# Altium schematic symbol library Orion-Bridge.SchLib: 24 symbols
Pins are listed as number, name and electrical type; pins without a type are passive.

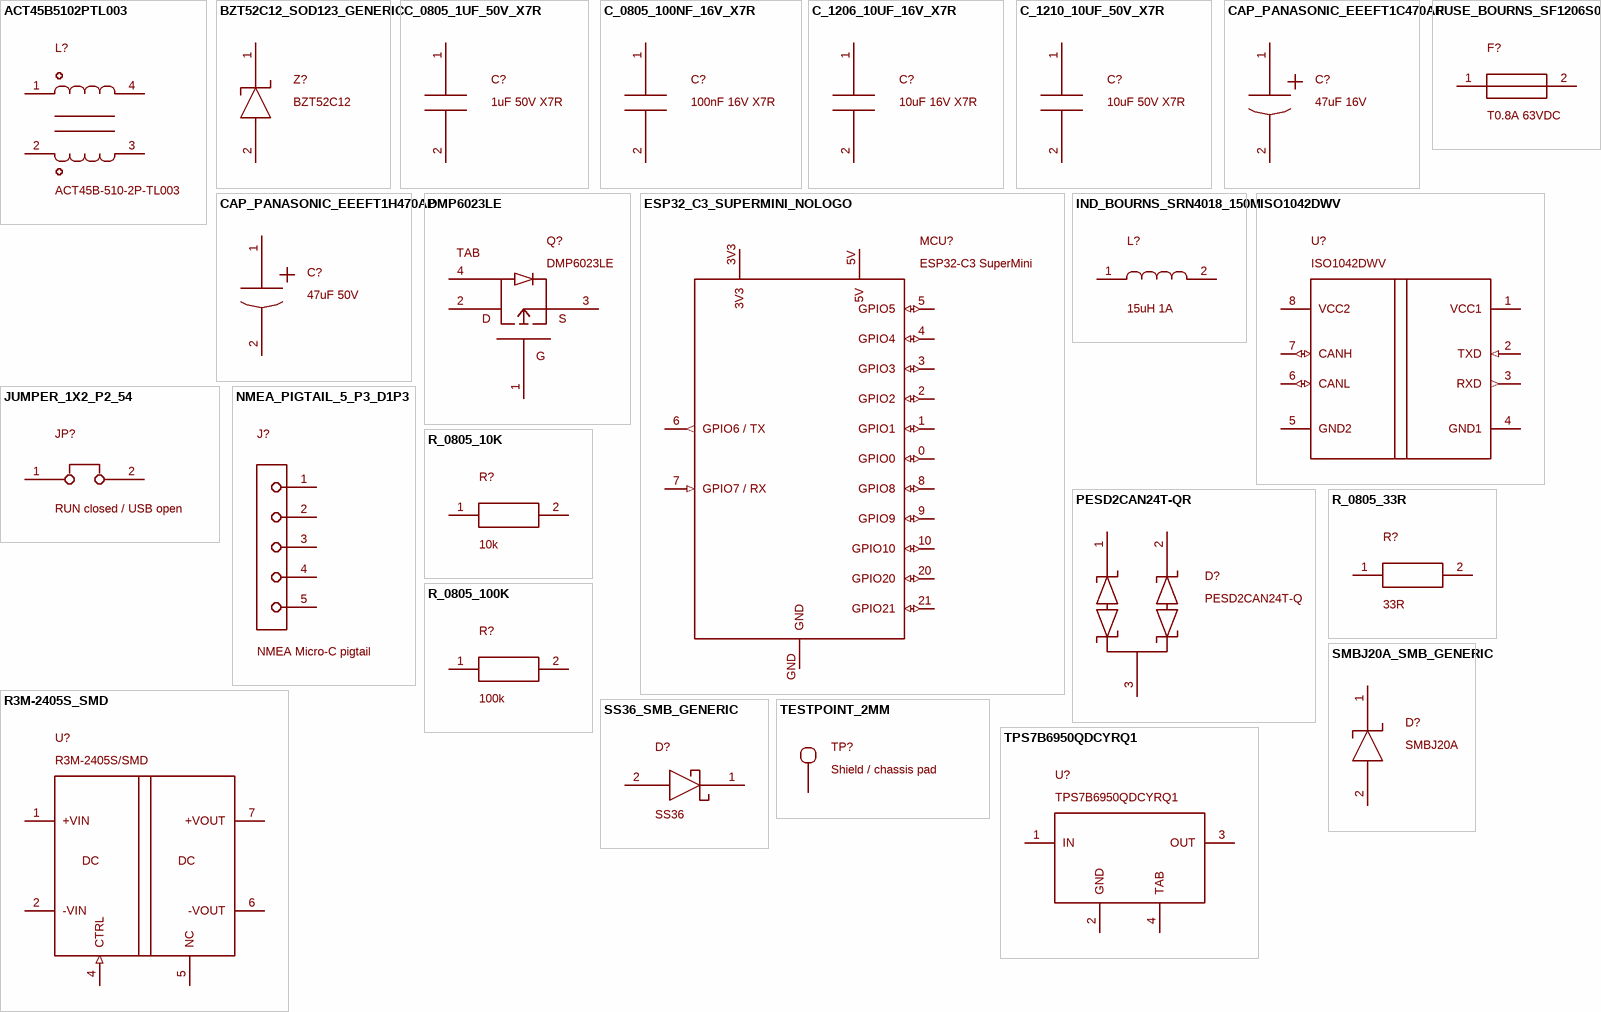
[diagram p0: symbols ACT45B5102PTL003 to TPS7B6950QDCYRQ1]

## ACT45B5102PTL003
designator L?, comment ACT45B-510-2P-TL003
Manufacturer: TDK; MPN: ACT45B5102PTL003
footprint ACT45B
pins: 1 H_EXT, 2 L_EXT, 3 L_IC, 4 H_IC

## BZT52C12_SOD123_GENERIC
designator Z?, comment BZT52C12
BZT52C12 - generic specification; manufacturer/MPN not selected
footprint SOD123
pins: 1 K, 2 A

## C_0805_1UF_50V_X7R
designator C?, comment 1uF 50V X7R
1uF 50V X7R - generic specification; manufacturer/MPN not selected
footprint C0805
pins: 1, 2

## C_0805_100NF_16V_X7R
designator C?, comment 100nF 16V X7R
100nF 16V X7R - generic specification; manufacturer/MPN not selected
footprint C0805
pins: 1, 2

## C_1206_10UF_16V_X7R
designator C?, comment 10uF 16V X7R
10uF 16V X7R - generic specification; manufacturer/MPN not selected
footprint C1206
pins: 1, 2

## C_1210_10UF_50V_X7R
designator C?, comment 10uF 50V X7R
10uF 50V X7R - generic specification; manufacturer/MPN not selected
footprint C1210
pins: 1, 2

## CAP_PANASONIC_EEEFT1C470AR
designator C?, comment 47uF 16V
47 uF 16 V FT-series SMD aluminum electrolytic, size B, standard product; Manufacturer: Panasonic Industry; MPN: EEEFT1C470AR
footprint PANASONIC_FT_D4
pins: 1 +, 2 -

## CAP_PANASONIC_EEEFT1H470AP
designator C?, comment 47uF 50V
47 uF 50 V FT-series SMD aluminum electrolytic, size D, standard product; Manufacturer: Panasonic Industry; MPN: EEEFT1H470AP
footprint PANASONIC_FT_D6P3
pins: 1 +, 2 -

## DMP6023LE
designator Q?
Manufacturer: Diodes Incorporated
footprint SOT223_DIODES_DMP6023LE
pins: 1 G, 2 D, 3 S, 4 TAB=D

## ESP32_C3_SUPERMINI_NOLOGO
designator MCU?, comment ESP32-C3 SuperMini
Nologo ESP32-C3 SuperMini module, two 1x8 carrier headers, GPIO6 TX / GPIO7 RX; Manufacturer: Nologo Tech
footprint NOLOGO_C3_SUPERMINI_THT_2X8
pins: 0 GPIO0 (io), 1 GPIO1 (io), 2 GPIO2 (io), 3 GPIO3 (io), 3V3 (power), 4 GPIO4 (io), 5 GPIO5 (io), 5V (power), 6 GPIO6 / TX (out), 7 GPIO7 / RX (in), 8 GPIO8 (io), 9 GPIO9 (io), 10 GPIO10 (io), 20 GPIO20 (io), 21 GPIO21 (io), GND (power)

## FUSE_BOURNS_SF1206S080
designator F?, comment T0.8A 63VDC
0.8 A slow-blow SMD ceramic fuse, 63 VDC, 50 A interrupt rating; Manufacturer: Bourns; MPN: SF-1206S080-2
footprint BOURNS_SF1206S
pins: 1, 2

## IND_BOURNS_SRN4018_150M
designator L?, comment 15uH 1A
15 uH semi-shielded power inductor, 1.0 A RMS and 1.1 A saturation rating; Manufacturer: Bourns; MPN: SRN4018-150M
footprint BOURNS_SRN4018
pins: 1, 2

## ISO1042DWV
designator U?
Manufacturer: Texas Instruments
footprint SOIC8_DWV
pins: 1 VCC1 (power), 2 TXD (in), 3 RXD (out), 4 GND1 (power), 5 GND2 (power), 6 CANL (io), 7 CANH (io), 8 VCC2 (power)

## JUMPER_1X2_P2_54
designator JP?, comment RUN closed / USB open
RUN closed / USB open - generic specification; manufacturer/MPN not selected
footprint HDR1X2_2.54
pins: 1, 2

## NMEA_PIGTAIL_5_P3_D1P3
designator J?, comment NMEA Micro-C pigtail
Five direct wire-solder pads for a separately selected Micro-C cable; this is a PCB interface, not an invented connector MPN or face view
footprint PIGTAIL_5_P3_D1P3
pins: 1 SHIELD, 2 NET-S, 3 NET-C, 4 CAN-H, 5 CAN-L

## PESD2CAN24T-QR
designator D?, comment PESD2CAN24T-Q
Manufacturer: Nexperia; MPN: PESD2CAN24T-QR
footprint SOT23_NEXPERIA_REFLOW
pins: 1 K1, 2 K2, 3 CC

## R3M-2405S_SMD
designator U?, comment R3M-2405S/SMD
Manufacturer: RECOM
footprint R3M_SMD
pins: 1 +VIN (power), 2 -VIN (power), 4 CTRL (in), 5 NC, 6 -VOUT (power), 7 +VOUT (power)

## R_0805_10K
designator R?, comment 10k
10k - generic specification; manufacturer/MPN not selected
footprint R0805
pins: 1, 2

## R_0805_33R
designator R?, comment 33R
33R - generic specification; manufacturer/MPN not selected
footprint R0805
pins: 1, 2

## R_0805_100K
designator R?, comment 100k
100k - generic specification; manufacturer/MPN not selected
footprint R0805
pins: 1, 2

## SMBJ20A_SMB_GENERIC
designator D?, comment SMBJ20A
SMBJ20A - generic specification; manufacturer/MPN not selected
footprint SMB
pins: 1 K, 2 A

## SS36_SMB_GENERIC
designator D?, comment SS36
SS36 - generic specification; manufacturer/MPN not selected
footprint SMB
pins: 1 K, 2 A

## TESTPOINT_2MM
designator TP?, comment Shield / chassis pad
Shield / chassis pad - generic specification; manufacturer/MPN not selected
footprint TESTPOINT_2MM
pins: 1 SHIELD

## TPS7B6950QDCYRQ1
designator U?
Manufacturer: Texas Instruments
footprint SOT223_LDO
pins: 1 IN (power), 2 GND (power), 3 OUT (power), 4 TAB (power)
